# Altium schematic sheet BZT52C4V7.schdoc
size 127 x 101 mm
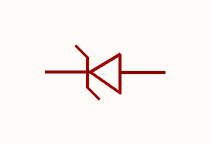
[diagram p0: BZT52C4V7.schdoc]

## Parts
ZD?  bzt52c4v7_c2116  [SOD-123_L2.8-W1.8-LS3.7-RD]  (value not drawn)

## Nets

Not connected (* = marked no-connect by the designer): ZD? 1(K) 2(A)

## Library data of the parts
ZD? = bzt52c4v7_c2116: 二极管配置:1个独立式;稳压值(标称值):4.7V;稳压值(范围值):4.4V~5V;耗散功率(Pd):500mW;; Manufacturer: CJ(江苏长电/长晶); AddInBom: yes; ModelId: 7884390a25fb4c08947731ebfba7e3f8; ModelTransform: 144.8816,62.992,0,0,0,0,0,0,0; Diode Configuration: 1个独立式; Zener Voltage(Nom): 4.7V; Reverse Leakage Current (Ir): 3uA; Pd - Power Dissipation: 500mW; Impedance(Zzt): 80Ω; Impedance(Zzk): 500Ω; Operating Junction Temperature Range: -55℃~+150℃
